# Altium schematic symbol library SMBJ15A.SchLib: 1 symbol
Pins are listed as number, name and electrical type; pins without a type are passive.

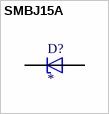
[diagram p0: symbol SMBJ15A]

## SMBJ15A
designator D?
600W, 17.6V, 5%, Unidirectional, TVS; MF: Taiwan Semiconductor; MP: SMBJ15A
footprint DIOM4336X265N
pins: A, C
